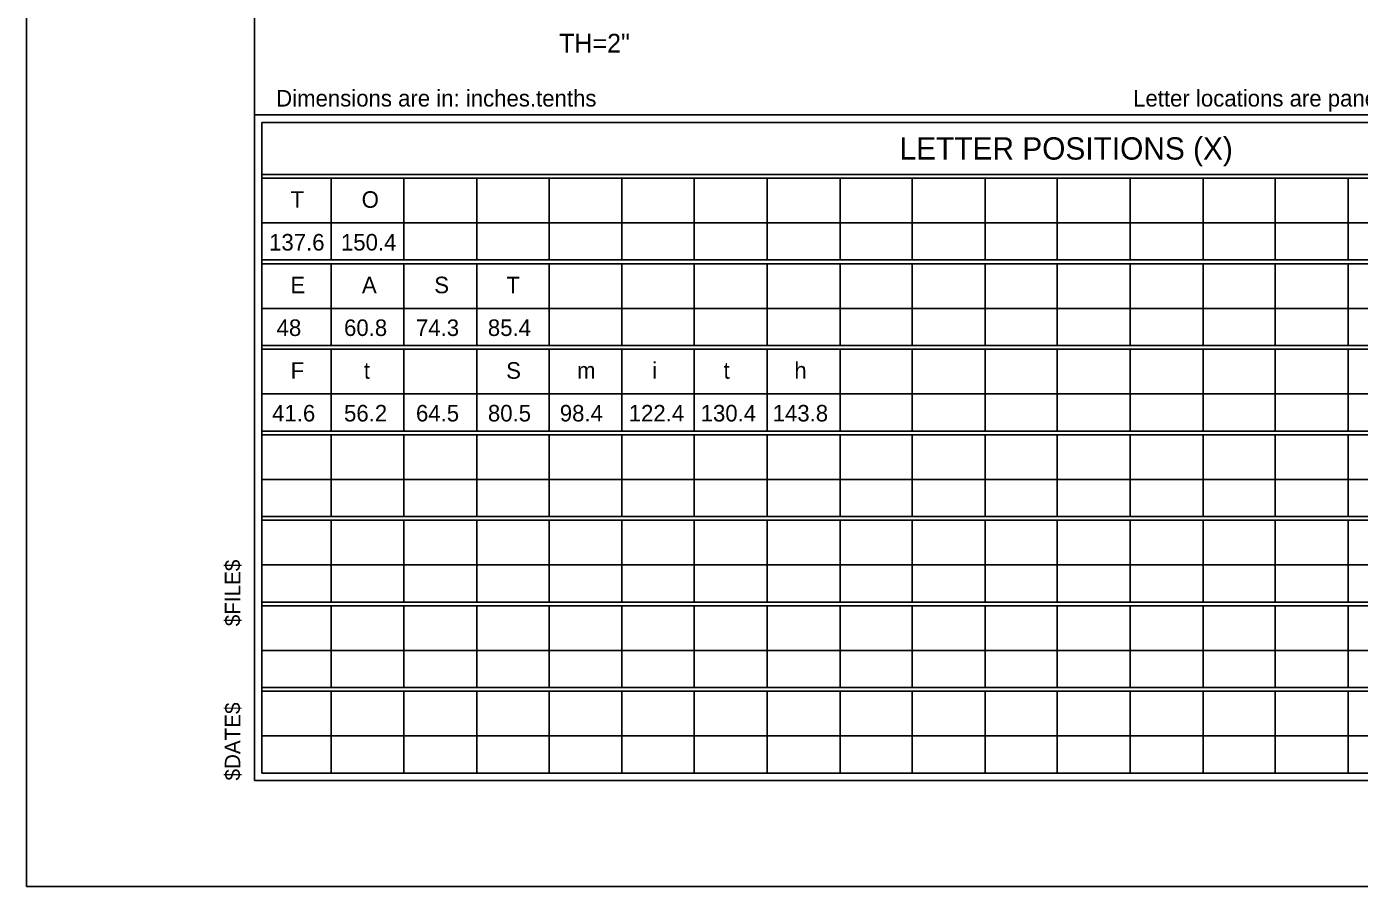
# Model space of a CAD drawing. Extents: x 2150010 to 2150174, y 145114 to 145224.
# Drawn here: x 2150010.46 to 2150051.99, y 145114.09 to 145140.9 of the extents above; entities that cross this region are included whole.
import ezdxf

# ---------------------------------------------------------------- set-up
doc = ezdxf.new("R2010")
doc.units = 0
for name, color, linetype in [('BORDER', 7, 'Continuous'), ('GSDIMS', 7, 'Continuous'), ('Level 1', 7, 'Continuous'), ('PDF', 7, 'Continuous')]:
    doc.layers.add(name, color=color, linetype=linetype)

msp = doc.modelspace()

# ---------------------------------------------------------------- linework, layer by layer
at = {"layer": 'BORDER'}
for p, q in [((2150010.458, 145219.948), (2150010.458, 145114.088)), ((2150017.557, 145216.512), (2150017.557, 145117.388)), ((2150017.557, 145117.388), (2150171.536, 145117.388)), ((2150010.458, 145114.088), (2150174.061, 145114.088))]:
    msp.add_line(p, q, dxfattribs=at)
at = {"layer": 'Level 1'}
for p, q in [((2150017.557, 145138.143), (2150062.583, 145138.143)), ((2150017.789, 145136.288), (2150076.084, 145136.288)), ((2150017.789, 145136.172), (2150076.084, 145136.172)), ((2150019.946, 145136.172), (2150019.946, 145133.621)), ((2150022.218, 145136.172), (2150022.218, 145133.621)), ((2150024.491, 145136.172), (2150024.491, 145133.621)), ((2150026.74, 145136.172), (2150026.74, 145133.621)), ((2150029.013, 145136.172), (2150029.013, 145133.621)), ((2150031.262, 145136.172), (2150031.262, 145133.621)), ((2150033.535, 145136.172), (2150033.535, 145133.621)), ((2150035.808, 145136.172), (2150035.808, 145133.621)), ((2150038.057, 145136.172), (2150038.057, 145133.621)), ((2150040.329, 145136.172), (2150040.329, 145133.621)), ((2150042.579, 145136.172), (2150042.579, 145133.621)), ((2150044.851, 145136.172), (2150044.851, 145133.621)), ((2150047.124, 145136.172), (2150047.124, 145133.621)), ((2150049.373, 145136.172), (2150049.373, 145133.621)), ((2150051.646, 145136.172), (2150051.646, 145133.621)), ((2150017.789, 145134.78), (2150067.426, 145134.78)), ((2150017.789, 145133.621), (2150076.084, 145133.621)), ((2150017.789, 145133.505), (2150076.084, 145133.505)), ((2150019.946, 145133.505), (2150019.946, 145130.954)), ((2150022.218, 145133.505), (2150022.218, 145130.954)), ((2150024.491, 145133.505), (2150024.491, 145130.954)), ((2150026.74, 145133.505), (2150026.74, 145130.954)), ((2150029.013, 145133.505), (2150029.013, 145130.954)), ((2150031.262, 145133.505), (2150031.262, 145130.954)), ((2150033.535, 145133.505), (2150033.535, 145130.954)), ((2150035.808, 145133.505), (2150035.808, 145130.954)), ((2150038.057, 145133.505), (2150038.057, 145130.954)), ((2150040.329, 145133.505), (2150040.329, 145130.954)), ((2150042.579, 145133.505), (2150042.579, 145130.954)), ((2150044.851, 145133.505), (2150044.851, 145130.954)), ((2150047.124, 145133.505), (2150047.124, 145130.954)), ((2150049.373, 145133.505), (2150049.373, 145130.954)), ((2150051.646, 145133.505), (2150051.646, 145130.954)), ((2150017.789, 145132.113), (2150067.426, 145132.113)), ((2150017.789, 145130.954), (2150076.084, 145130.954)), ((2150017.789, 145130.838), (2150076.084, 145130.838)), ((2150019.946, 145130.838), (2150019.946, 145128.287)), ((2150022.218, 145130.838), (2150022.218, 145128.287)), ((2150024.491, 145130.838), (2150024.491, 145128.287)), ((2150026.74, 145130.838), (2150026.74, 145128.287)), ((2150029.013, 145130.838), (2150029.013, 145128.287)), ((2150031.262, 145130.838), (2150031.262, 145128.287)), ((2150033.535, 145130.838), (2150033.535, 145128.287)), ((2150035.808, 145130.838), (2150035.808, 145128.287)), ((2150038.057, 145130.838), (2150038.057, 145128.287)), ((2150040.329, 145130.838), (2150040.329, 145128.287)), ((2150042.579, 145130.838), (2150042.579, 145128.287)), ((2150044.851, 145130.838), (2150044.851, 145128.287)), ((2150047.124, 145130.838), (2150047.124, 145128.287)), ((2150049.373, 145130.838), (2150049.373, 145128.287)), ((2150051.646, 145130.838), (2150051.646, 145128.287)), ((2150017.789, 145129.447), (2150067.426, 145129.447)), ((2150017.789, 145128.287), (2150076.084, 145128.287)), ((2150017.789, 145128.171), (2150076.084, 145128.171)), ((2150019.946, 145128.171), (2150019.946, 145125.62)), ((2150022.218, 145128.171), (2150022.218, 145125.62)), ((2150024.491, 145128.171), (2150024.491, 145125.62)), ((2150026.74, 145128.171), (2150026.74, 145125.62)), ((2150029.013, 145128.171), (2150029.013, 145125.62)), ((2150031.262, 145128.171), (2150031.262, 145125.62)), ((2150033.535, 145128.171), (2150033.535, 145125.62)), ((2150035.808, 145128.171), (2150035.808, 145125.62)), ((2150038.057, 145128.171), (2150038.057, 145125.62)), ((2150040.329, 145128.171), (2150040.329, 145125.62)), ((2150042.579, 145128.171), (2150042.579, 145125.62)), ((2150044.851, 145128.171), (2150044.851, 145125.62)), ((2150047.124, 145128.171), (2150047.124, 145125.62)), ((2150049.373, 145128.171), (2150049.373, 145125.62)), ((2150051.646, 145128.171), (2150051.646, 145125.62)), ((2150017.789, 145126.78), (2150067.426, 145126.78)), ((2150017.789, 145125.62), (2150076.084, 145125.62)), ((2150017.789, 145125.504), (2150076.084, 145125.504)), ((2150019.946, 145125.504), (2150019.946, 145122.954)), ((2150022.218, 145125.504), (2150022.218, 145122.954)), ((2150024.491, 145125.504), (2150024.491, 145122.954)), ((2150026.74, 145125.504), (2150026.74, 145122.954)), ((2150029.013, 145125.504), (2150029.013, 145122.954)), ((2150031.262, 145125.504), (2150031.262, 145122.954)), ((2150033.535, 145125.504), (2150033.535, 145122.954)), ((2150035.808, 145125.504), (2150035.808, 145122.954)), ((2150038.057, 145125.504), (2150038.057, 145122.954)), ((2150040.329, 145125.504), (2150040.329, 145122.954)), ((2150042.579, 145125.504), (2150042.579, 145122.954)), ((2150044.851, 145125.504), (2150044.851, 145122.954)), ((2150047.124, 145125.504), (2150047.124, 145122.954)), ((2150049.373, 145125.504), (2150049.373, 145122.954)), ((2150051.646, 145125.504), (2150051.646, 145122.954)), ((2150017.789, 145124.113), (2150067.426, 145124.113)), ((2150017.789, 145122.954), (2150076.084, 145122.954)), ((2150017.789, 145122.838), (2150076.084, 145122.838)), ((2150019.946, 145122.838), (2150019.946, 145120.287)), ((2150022.218, 145122.838), (2150022.218, 145120.287)), ((2150024.491, 145122.838), (2150024.491, 145120.287)), ((2150026.74, 145122.838), (2150026.74, 145120.287)), ((2150029.013, 145122.838), (2150029.013, 145120.287)), ((2150031.262, 145122.838), (2150031.262, 145120.287)), ((2150033.535, 145122.838), (2150033.535, 145120.287)), ((2150035.808, 145122.838), (2150035.808, 145120.287)), ((2150038.057, 145122.838), (2150038.057, 145120.287)), ((2150040.329, 145122.838), (2150040.329, 145120.287)), ((2150042.579, 145122.838), (2150042.579, 145120.287)), ((2150044.851, 145122.838), (2150044.851, 145120.287)), ((2150047.124, 145122.838), (2150047.124, 145120.287)), ((2150049.373, 145122.838), (2150049.373, 145120.287)), ((2150051.646, 145122.838), (2150051.646, 145120.287)), ((2150017.789, 145121.446), (2150067.426, 145121.446)), ((2150017.789, 145120.287), (2150076.084, 145120.287)), ((2150017.789, 145120.171), (2150076.084, 145120.171)), ((2150019.946, 145120.171), (2150019.946, 145117.62)), ((2150022.218, 145120.171), (2150022.218, 145117.62)), ((2150024.491, 145120.171), (2150024.491, 145117.62)), ((2150026.74, 145120.171), (2150026.74, 145117.62)), ((2150029.013, 145120.171), (2150029.013, 145117.62)), ((2150031.262, 145120.171), (2150031.262, 145117.62)), ((2150033.535, 145120.171), (2150033.535, 145117.62)), ((2150035.808, 145120.171), (2150035.808, 145117.62)), ((2150038.057, 145120.171), (2150038.057, 145117.62)), ((2150040.329, 145120.171), (2150040.329, 145117.62)), ((2150042.579, 145120.171), (2150042.579, 145117.62)), ((2150044.851, 145120.171), (2150044.851, 145117.62)), ((2150047.124, 145120.171), (2150047.124, 145117.62)), ((2150049.373, 145120.171), (2150049.373, 145117.62)), ((2150051.646, 145120.171), (2150051.646, 145117.62)), ((2150017.789, 145118.779), (2150067.426, 145118.779))]:
    msp.add_line(p, q, dxfattribs=at)
msp.add_lwpolyline([(2150017.789, 145137.911), (2150076.084, 145137.911), (2150076.084, 145117.62), (2150017.789, 145117.62)], close=True, dxfattribs=at)
at = {"layer": 'PDF'}
msp.add_lwpolyline([(2150010.458, 145114.088), (2150174.061, 145114.088), (2150174.061, 145219.948), (2150010.458, 145219.948)], close=True, dxfattribs=at)

# ---------------------------------------------------------------- texts
at = {"layer": 'BORDER'}
for s, p in [('$FILE$', (2150017.115, 145122.2)), ('$DATE$', (2150017.115, 145117.389))]:
    msp.add_text(s, height=0.4812, rotation=90, dxfattribs=at).set_placement(p)
at = {"layer": 'GSDIMS'}
msp.add_text('TH=2"', height=0.5833, dxfattribs=at).set_placement((2150027.054, 145140.091))
at = {"layer": 'Level 1'}
for s, height, p in [('Dimensions are in: inches.tenths', 0.51652, (2150018.235, 145138.406)), ('Letter locations are panel edge to lower left corner', 0.51652, (2150044.943, 145138.406)), ('LETTER POSITIONS (X)', 0.69555, (2150037.664, 145136.751)), ('T', 0.517, (2150018.683, 145135.248)), ('O', 0.517, (2150020.899, 145135.248)), ('137.6', 0.5165, (2150018.014, 145133.916)), ('150.4', 0.5165, (2150020.254, 145133.916)), ('S', 0.517, (2150023.162, 145132.583)), ('E', 0.517, (2150018.678, 145132.583)), ('A', 0.517, (2150020.908, 145132.583)), ('T', 0.517, (2150025.409, 145132.583)), ('48', 0.5165, (2150018.249, 145131.251)), ('60.8', 0.5165, (2150020.35, 145131.251)), ('74.3', 0.5165, (2150022.592, 145131.251)), ('85.4', 0.5165, (2150024.832, 145131.251)), ('F', 0.517, (2150018.687, 145129.917)), ('t', 0.517, (2150020.967, 145129.917)), ('S', 0.517, (2150025.404, 145129.917)), ('m', 0.517, (2150027.613, 145129.917)), ('i', 0.517, (2150029.956, 145129.917)), ('t', 0.517, (2150032.177, 145129.918)), ('h', 0.517, (2150034.383, 145129.917)), ('41.6', 0.5165, (2150018.108, 145128.585)), ('56.2', 0.5165, (2150020.35, 145128.585)), ('64.5', 0.5165, (2150022.592, 145128.585)), ('80.5', 0.5165, (2150024.834, 145128.585)), ('98.4', 0.5165, (2150027.074, 145128.585)), ('122.4', 0.5165, (2150029.222, 145128.585)), ('130.4', 0.5165, (2150031.464, 145128.585)), ('143.8', 0.5165, (2150033.708, 145128.585))]:
    msp.add_text(s, height=height, dxfattribs=at).set_placement(p)

doc.saveas('drawing.dxf')
